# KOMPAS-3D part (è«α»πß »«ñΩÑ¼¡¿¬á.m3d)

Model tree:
1. Эскиз:1
2. Операция выдавливания:1
     Расстояние 1 = 8.5
3. Эскиз:2
4. Операция выдавливания:2
     Расстояние 1 = 3
5. Эскиз:3
6. Смещенная плоскость:1
     Расстояние = 3.4415
7. Эскиз:4
8. Смещенная плоскость:2
     Расстояние = 11.75
9. Эскиз:5
10. Операция по сечениям:1
11. Смещенная плоскость:3
     Расстояние = 11.5
12. Эскиз:6
13. Вырезать элемент выдавливания:1
     Расстояние 2 = 5.75; Расстояние 1 = 10
14. Эскиз:7
15. Операция выдавливания:3
     Расстояние 1 = 14.65
16. Эскиз:8
17. Вырезать элемент выдавливания:2
     Расстояние 2 = 8.65; Расстояние 1 = 8.65
18. Эскиз:9
19. Вырезать элемент выдавливания:3
     Расстояние 2 = 8.65; Расстояние 1 = 12.75
20. Эскиз:10
21. Вырезать элемент выдавливания:4
     Расстояние 2 = 8.65; Расстояние 1 = 5
22. Эскиз:11
23. Вырезать элемент выдавливания:5
     Расстояние 2 = 8.65; Расстояние 1 = 43.5
24. Эскиз:12
25. Вырезать элемент выдавливания:6
     Расстояние 2 = 15; Расстояние 1 = 15
26. Смещенная плоскость:4
     Расстояние = 21.85
27. Эскиз:13
28. Эскиз:14
29. Эскиз:15
30. Операция выдавливания:4
     Расстояние 1 = 21.85
31. Эскиз:17
32. Операция выдавливания:5
     Расстояние 1 = 66.25
33. Эскиз:18
34. Операция вращения:1
     Угол 1 = 158; Угол 2 = 158
35. Эскиз:19
36. Вырезать элемент выдавливания:8
     Расстояние 2 = 15; Расстояние 1 = 12
37. Эскиз:20
38. Вырезать элемент выдавливания:9
     Расстояние 2 = 15; Расстояние 1 = 12
39. Эскиз:21
40. Вырезать элемент выдавливания:10
     Расстояние 2 = 15; Расстояние 1 = 12
41. Смещенная плоскость:5
     Расстояние = 12
42. Эскиз:22
43. Вырезать элемент выдавливания:11
     Расстояние 2 = 9.5; Расстояние 1 = 12
44. Скругление:1
     Радиус = 0.5
45. Скругление:2
     Радиус = 1.5
46. Скругление:3
     Радиус = 0.5
47. Скругление:4
     Радиус = 0.75
48. Скругление:5
     Радиус = 1
49. Скругление:6
     Радиус = 1
50. Фаска:1
     Угол = 45; Длина 1 = 0.75; Длина 2 = 0.75
51. Фаска:2
     Угол = 45; Длина 1 = 1; Длина 2 = 1
